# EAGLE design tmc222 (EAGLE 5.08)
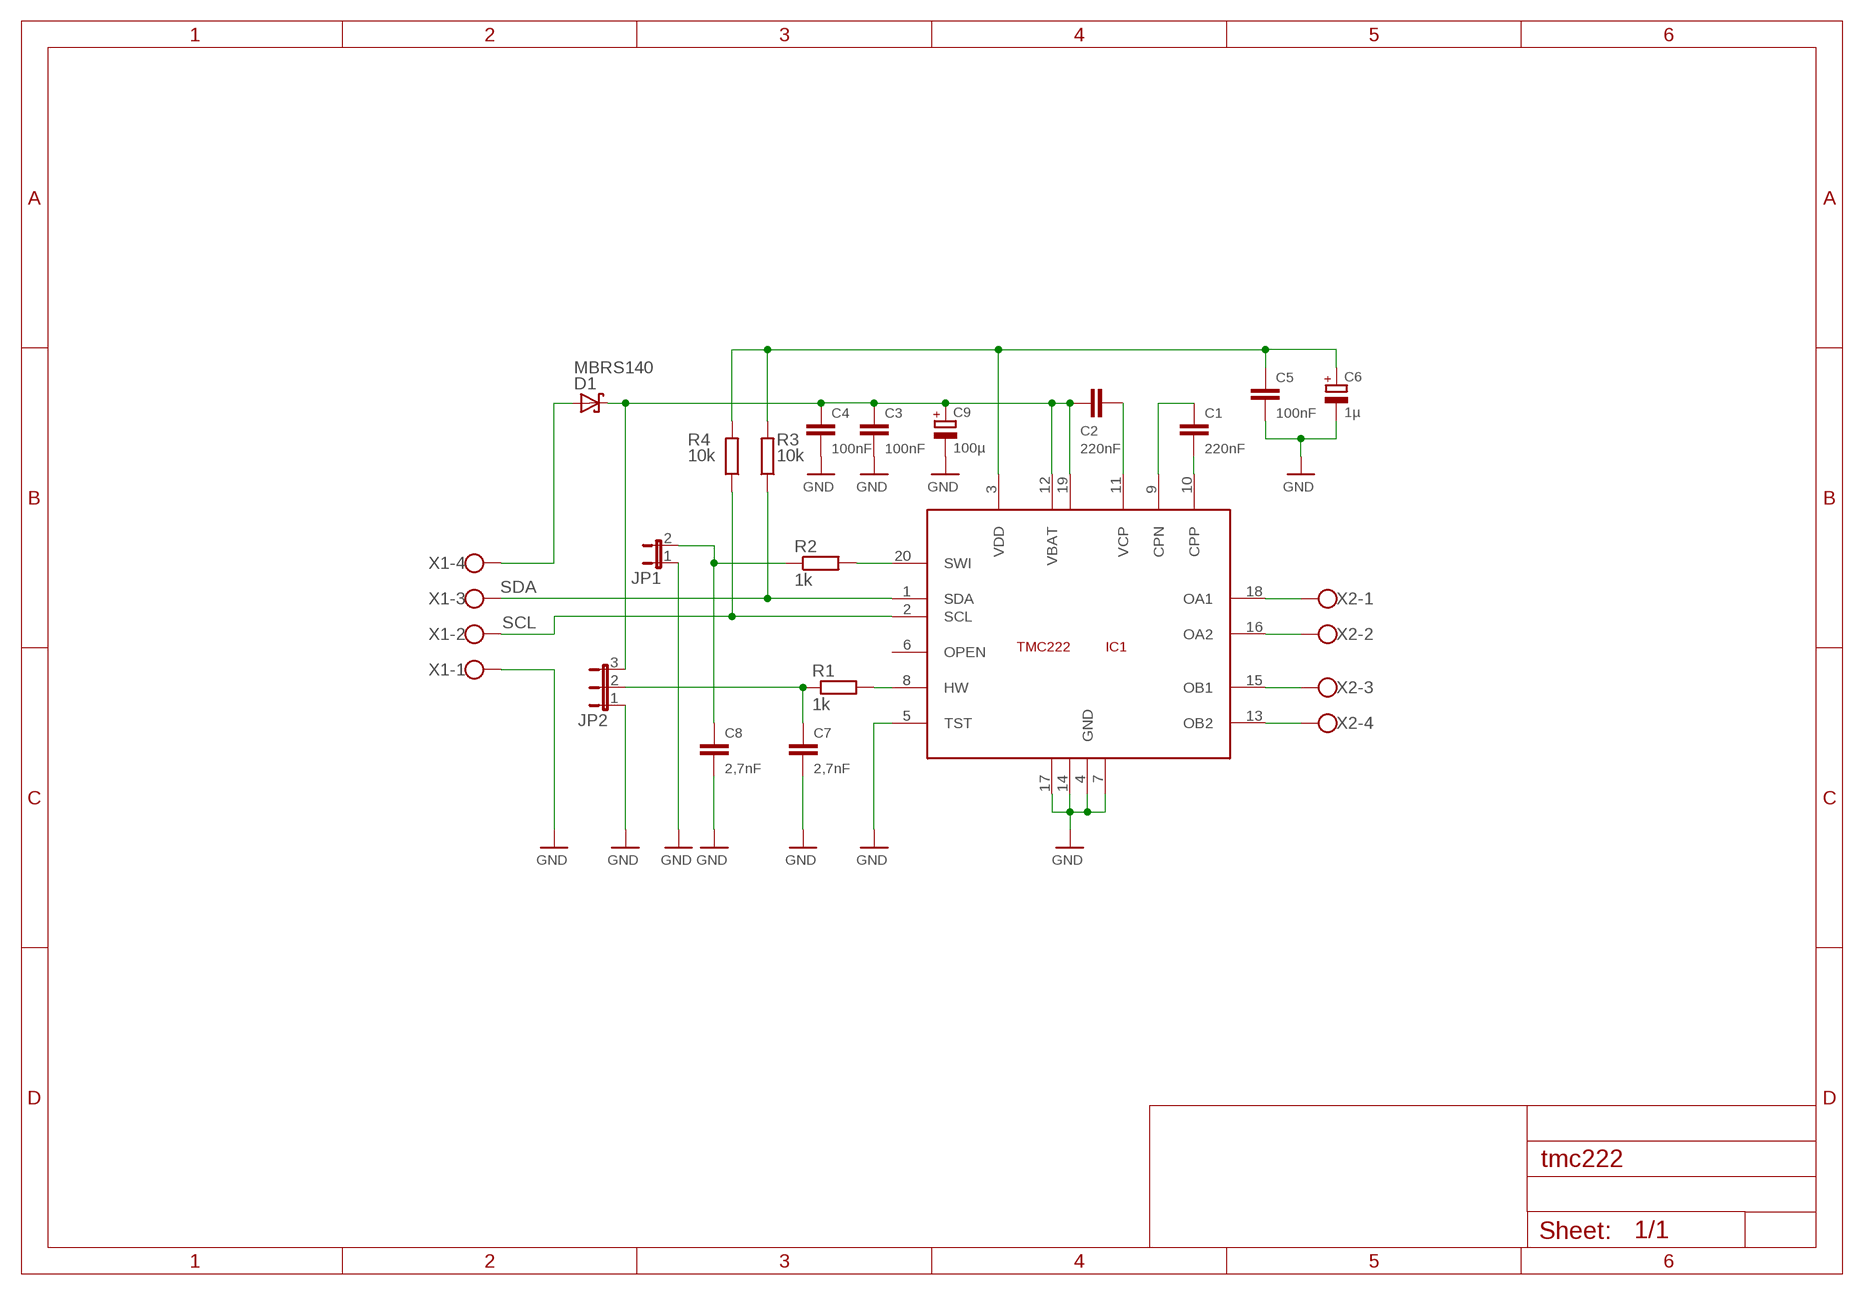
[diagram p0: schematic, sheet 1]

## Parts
C1  220nF  C-EUC0805  [C0805]
C2  220nF  C-EUC0805  [C0805]
C3  100nF  C-EUC0805  [C0805]
C4  100nF  C-EUC0805  [C0805]
C5  100nF  C-EUC0805  [C0805]
C6  1µ  CPOL-EUB/3528-21R  [B/3528-21R]
C7  2,7nF  C-EUC0805  [C0805]
C8  2,7nF  C-EUC0805  [C0805]
C9  100µ  CPOL-EUE5-10.5  [E5-10,5]
D1  MBRS140  SCHOTTKY-DIODESMD  [SMB]
IC1  TMC222  [SOIC20]
JP1  JP1E  [JP1]
JP2  JP2E  [JP2]
R1  1k  R-EU_R0805  [R0805]
R2  1k  R-EU_R0805  [R0805]
R3  10k  R-EU_R0805  [R0805]
R4  10k  R-EU_R0805  [R0805]
X1  W237-04P  [W237-4P]
X2  W237-04P  [W237-4P]

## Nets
GND: C3.2 C4.2 C5.2 C6.- C7.2 C8.2 C9.- IC1.4(GND) IC1.5(TST) IC1.7(GND2) IC1.14(GND3) IC1.17(GND4) JP1.1 JP2.1 X1.1
N$2: C1.1 IC1.9(CPN)
N$3: C1.2 IC1.10(CPP)
N$4: C2.2 IC1.11(VCP)
N$5: C2.1 C3.1 C4.1 C9.+ D1.C IC1.12(VBAT) IC1.19(VBAT2) JP2.3
N$6: IC1.8(HW) R1.2
N$7: C7.1 JP2.2 R1.1
N$8: C8.1 JP1.2 R2.1
N$9: IC1.20(SWI) R2.2
N$10: IC1.13(OB2) X2.4
N$11: IC1.15(OB1) X2.3
N$12: IC1.16(OA2) X2.2
N$13: IC1.18(OA1) X2.1
N$17: D1.A X1.4
N$18: C5.1 C6.+ IC1.3(VDD) R3.2 R4.2
SCL: IC1.2(SCL) R4.1 X1.2
SDA: IC1.1(SDA) R3.1 X1.3
Unconnected: IC1.6(OPEN)

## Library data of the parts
C1-C5 C7 C8 = rcl:C-EU: CAPACITOR, European symbol
C6 C9 = rcl:CPOL-EU: POLARIZED CAPACITOR, European symbol
D1 = diode:SCHOTTKY-DIODE: Schottky Diode
IC1 = tmc:TMC222: TMC222 Micro Stepping Stepper Motor Controller / Driver with Two Wire Serial Interface
JP1 = jumper:JP1E: JUMPER
JP2 = jumper:JP2E: JUMPER
R1-R4 = rcl:R-EU_: RESISTOR, European symbol
X1 X2 = con-wago-508:W237-04P: WAGO SREW CLAMP

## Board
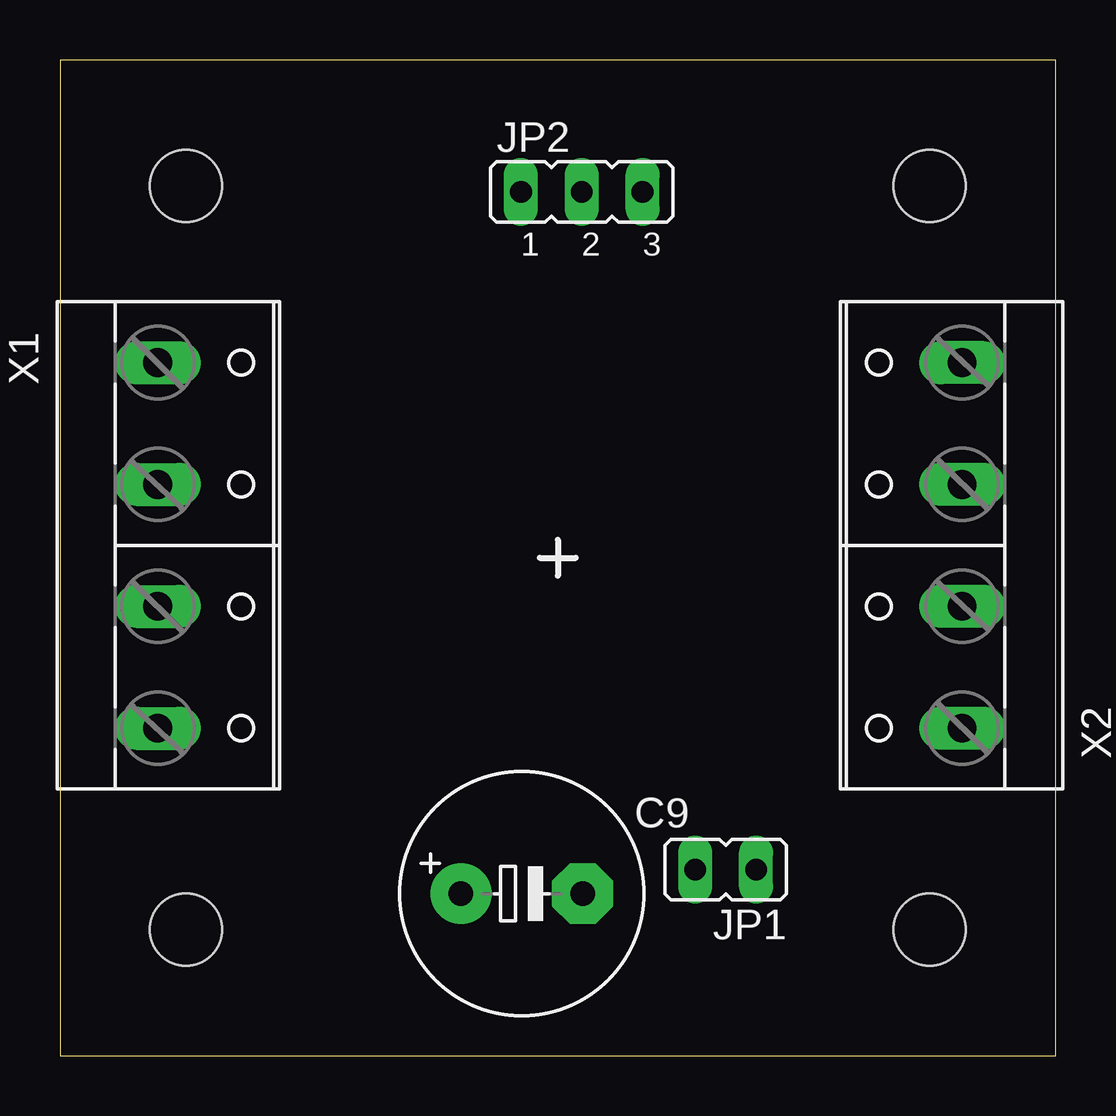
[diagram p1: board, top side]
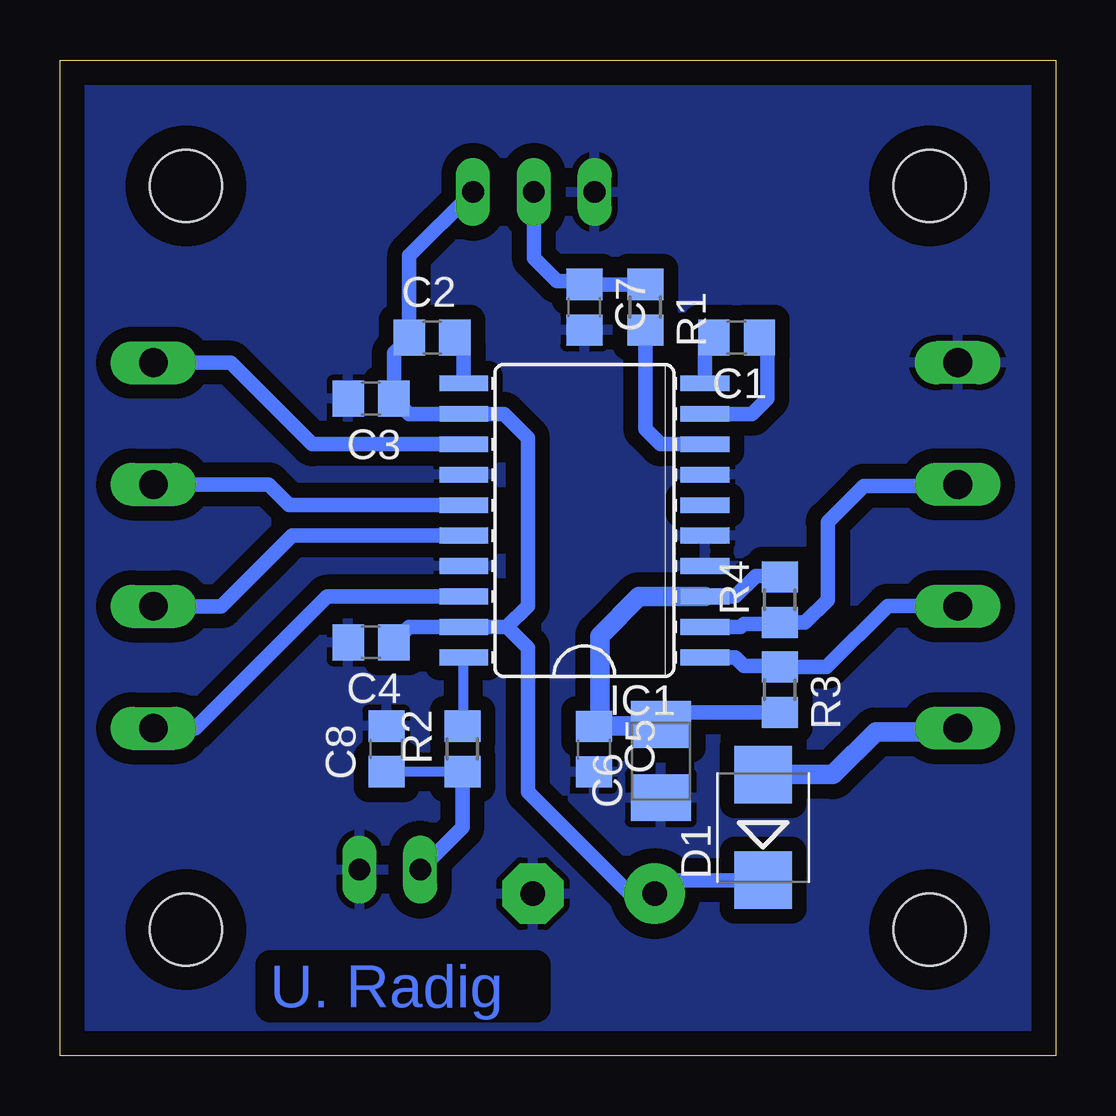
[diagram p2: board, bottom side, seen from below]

Size 41.5 x 41.5 mm. Coordinates in mm from the lower left corner, seen from the top.
Outline: 0,0 41.5,0 41.5,41.5 0,41.5 0,0
Copper layers (1*16): Top 0.035mm / dielectric 1.5mm / Bottom 0.035mm
Design rules "default": minimum track width 10mil, minimum drill 24mil, track to track 8mil, track to pad 8mil, pad to pad 8mil, via to via 8mil, smd to smd 8mil, copper to edge 40mil, drill to drill 8mil, minimum pad ring 10mil, minimum via ring 8mil, stop-mask expansion 4mil, vias tented up to drill 0mil, thermal gap 10mil
Holes 3 mm at 5.25,5.25 36.25,36.25 5.25,36.25 36.25,5.25

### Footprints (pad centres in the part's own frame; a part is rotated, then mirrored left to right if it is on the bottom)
C0805 = smd 1.3 x 1.5: 1 -0.95,0; 2 0.95,0
B/3528-21R = smd 1.95 x 2.5: + 1.525,0; - -1.525,0
E5-10,5 = drill 1.016 pad 2.54 round: + -2.54,0 | drill 1.016 pad 2.54 octagon: - 2.54,0
SMB = smd 2.4 x 2.4: A 2.2,0; C -2.2,0
SOIC20 = smd 0.66 x 2.032: 1 -5.715,-5.029; 2 -4.445,-5.029; 3 -3.175,-5.029; 4 -1.905,-5.029; 5 -0.635,-5.029; 6 0.635,-5.029; 7 1.905,-5.029; 8 3.175,-5.029; 9 4.445,-5.029; 10 5.715,-5.029; 11 5.715,5.029; 12 4.445,5.029; 13 3.175,5.029; 14 1.905,5.029; 15 0.635,5.029; 16 -0.635,5.029; 17 -1.905,5.029; 18 -3.175,5.029; 19 -4.445,5.029; 20 -5.715,5.029
JP1 = drill 0.914 long: 1 0,-1.27; 2 0,1.27
JP2 = drill 0.914 long: 1 -2.54,0; 2 0,0; 3 2.54,0
R0805 = smd 1.3 x 1.5: 1 -0.95,0; 2 0.95,0
W237-4P = drill 1.194 long: 1 -7.62,-0.635; 2 -2.54,-0.635; 3 2.54,-0.635; 4 7.62,-0.635

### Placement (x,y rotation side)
C1  13.29,29.93 180 bottom
C2  25.99,29.93 0 bottom
C3  28.53,27.39 180 bottom
C4  28.53,17.23 180 bottom
C5  19.24,12.78 270 bottom
C6  16.45,12.28 90 bottom
C7  19.64,31.2 270 bottom
C8  27.89,12.78 90 bottom
C9  19.25,6.75 0 top
D1  12.2,9.51 90 bottom
IC1  19.64,22.3 90 bottom
JP1  27.75,7.75 90 top
JP2  21.75,36 0 top
R1  17.1,31.2 270 bottom
R2  24.72,12.78 90 bottom
R3  11.5,15.25 270 bottom
R4  11.5,19 90 bottom
X1  4.71,21.27 270 top
X2  36.98,21.27 90 top

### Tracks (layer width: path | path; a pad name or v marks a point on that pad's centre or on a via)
GND
  pour Bottom (isolate 0.61): -0.37,-0.07 41.55,-0.07 41.55,41.64 -0.37,41.64
N$2
  Bottom 0.406: 12.02,29.61 C1.1
  Bottom 0.61: IC1.9 12.65,26.75 12.02,27.39 12.02,29.61
N$3
  Bottom 0.406: C1.2 14.61,29.55
  Bottom 0.61: 14.61,29.55 IC1.10
N$4
  Bottom 0.406: C2.2 24.67,29.55
  Bottom 0.61: 24.67,29.55 IC1.11
N$5
  Bottom 0.61: C4.1 26.95,17.86 IC1.19 22.89,17.86 | 22.89,17.86 22,18.75 22,25.75 23,26.75 IC1.12 26.95,26.75 C3.1 27.58,29.29 C2.1 26.94,33.35 JP2.3 | D1.C 16.65,7.31 C9.+ 17.75,6.75 22,11 22,17 22.86,17.86 22.89,17.86
N$6
  Bottom 0.61: IC1.8 16.46,25.48 17.1,26.11 R1.2
N$7
  Bottom 0.61: R1.1 C7.1 19.77,32.27 20.77,32.27 21.75,33.25 JP2.2
N$8
  Bottom 0.406: R2.1 C8.1
  Bottom 0.61: JP1.2 24.72,9.51 R2.1
N$9
  Bottom 0.406: IC1.20 24.67,13.78 R2.2
N$10
  Bottom 0.61: IC1.13 30.98,25.48 34.38,28.89 X2.4
N$11
  Bottom 0.61: IC1.15 31.94,22.94 32.8,23.8 X2.3
N$12
  Bottom 0.61: IC1.16 31.83,21.67 34.77,18.73 X2.2
N$13
  Bottom 0.61: IC1.18 30.37,19.13 35.85,13.64 X2.1
N$17
  Bottom 0.406: X1.4 4.22,13.5
  Bottom 0.813: D1.A 9.29,11.71 7.5,13.5 4.22,13.5
N$18
  Bottom 0.406: 19,13.73 C5.1 | C6.+ 16.52,13.73
  Bottom 0.61: IC1.3 13.37,19.13 12.5,20 11.55,20 R4.2 | R3.2 15.95,14.3 C6.+
  Bottom 0.813: IC1.3 17.37,19.13 19,17.5 19,13.73 16.52,13.73
SCL
  Bottom 0.61: IC1.2 13.14,17.86 13,18 11.55,18 R4.1 10.45,18.05 9.5,19 9.5,22.25 8,23.75 4.13,23.75 X1.2
SDA
  Bottom 0.61: IC1.1 13.34,16.59 13,16.25 11.55,16.25 R3.1 9.55,16.2 7,18.75 4.1,18.75 X1.3

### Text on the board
Bottom: U. Radig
